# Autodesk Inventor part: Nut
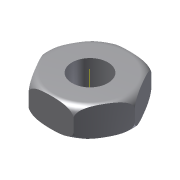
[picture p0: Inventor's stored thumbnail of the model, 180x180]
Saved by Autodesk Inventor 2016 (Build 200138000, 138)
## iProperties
Created: 2009-04
Part Number: Nut
Document SubType Name: Modeling
Designer: Sham
Density: 1 g/cm^3
Material: Generic
Mass: 4.65064 g
Surface Area: 21.3319 cm^2
Volume: 4.65064 cm^3
Appearance: Default
Author: Sham
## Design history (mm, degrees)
sketch "Sketch1"
  geometry: L1 (7.5, 12.99)-(15, 0); L2 (15, 0)-(7.5, -12.99); L3 (7.5, -12.99)-(-7.5, -12.99); L4 (-7.5, -12.99)-(-15, 0); L5 (-15, 0)-(-7.5, 12.99); L6 (-7.5, 12.99)-(7.5, 12.99); C1 r 6 at (0, 0); 1 further point
  constraints: 12 end point, 1 centre point, 1 coincident, 13 other
  dimensions: "d0" = 30 distance of L1.end L4.end; "d1" = 12 diameter of C1
extrude "Extrusion1" new body sketch "Sketch1" distance "d2" = 12; taper "d3" = 0 deg
sketch "Sketch2"
  geometry: L1 (-12, 0)-(-12, -0.022); L2 (-15, 7)-(-15, 3); L3 (0, -2.87)-(0, 12.87) reference; A1 r 3 centre (-12, 7) between (-12, 10) and (-15, 7); A2 r 3 centre (-12, 3) between (-15, 3) and (-12, 0)
  constraints: 4 end point, 4 point on circle, 2 centre point, 1 tangent
revolve "Revolution1" sketch "Sketch2" stored, may be unused: angle "d7" = 90 deg
body "Solid1"
other parameters: "d6" = 90 deg
